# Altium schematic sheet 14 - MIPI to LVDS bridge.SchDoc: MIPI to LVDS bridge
size A3; PageSetup: Record=PageOptions¦CenterHorizontal=True¦CenterVertical=True¦PrintScale=0.70¦XCorrection=1.00¦YCorrection=1.00¦PrintKind=0¦BorderSize=5000000¦LeftOffset=0¦BottomOffset=0¦Orientation=2¦PaperLength=4200¦PaperWidth=2970¦Scale=100¦PaperSource=7¦PrintQuality=600¦MediaType=1¦DitherType=10¦PaperKind=A4¦PrintScaleMode=1; Author: Juan Anzola; SheetNumber: 14; SheetTotal: 21
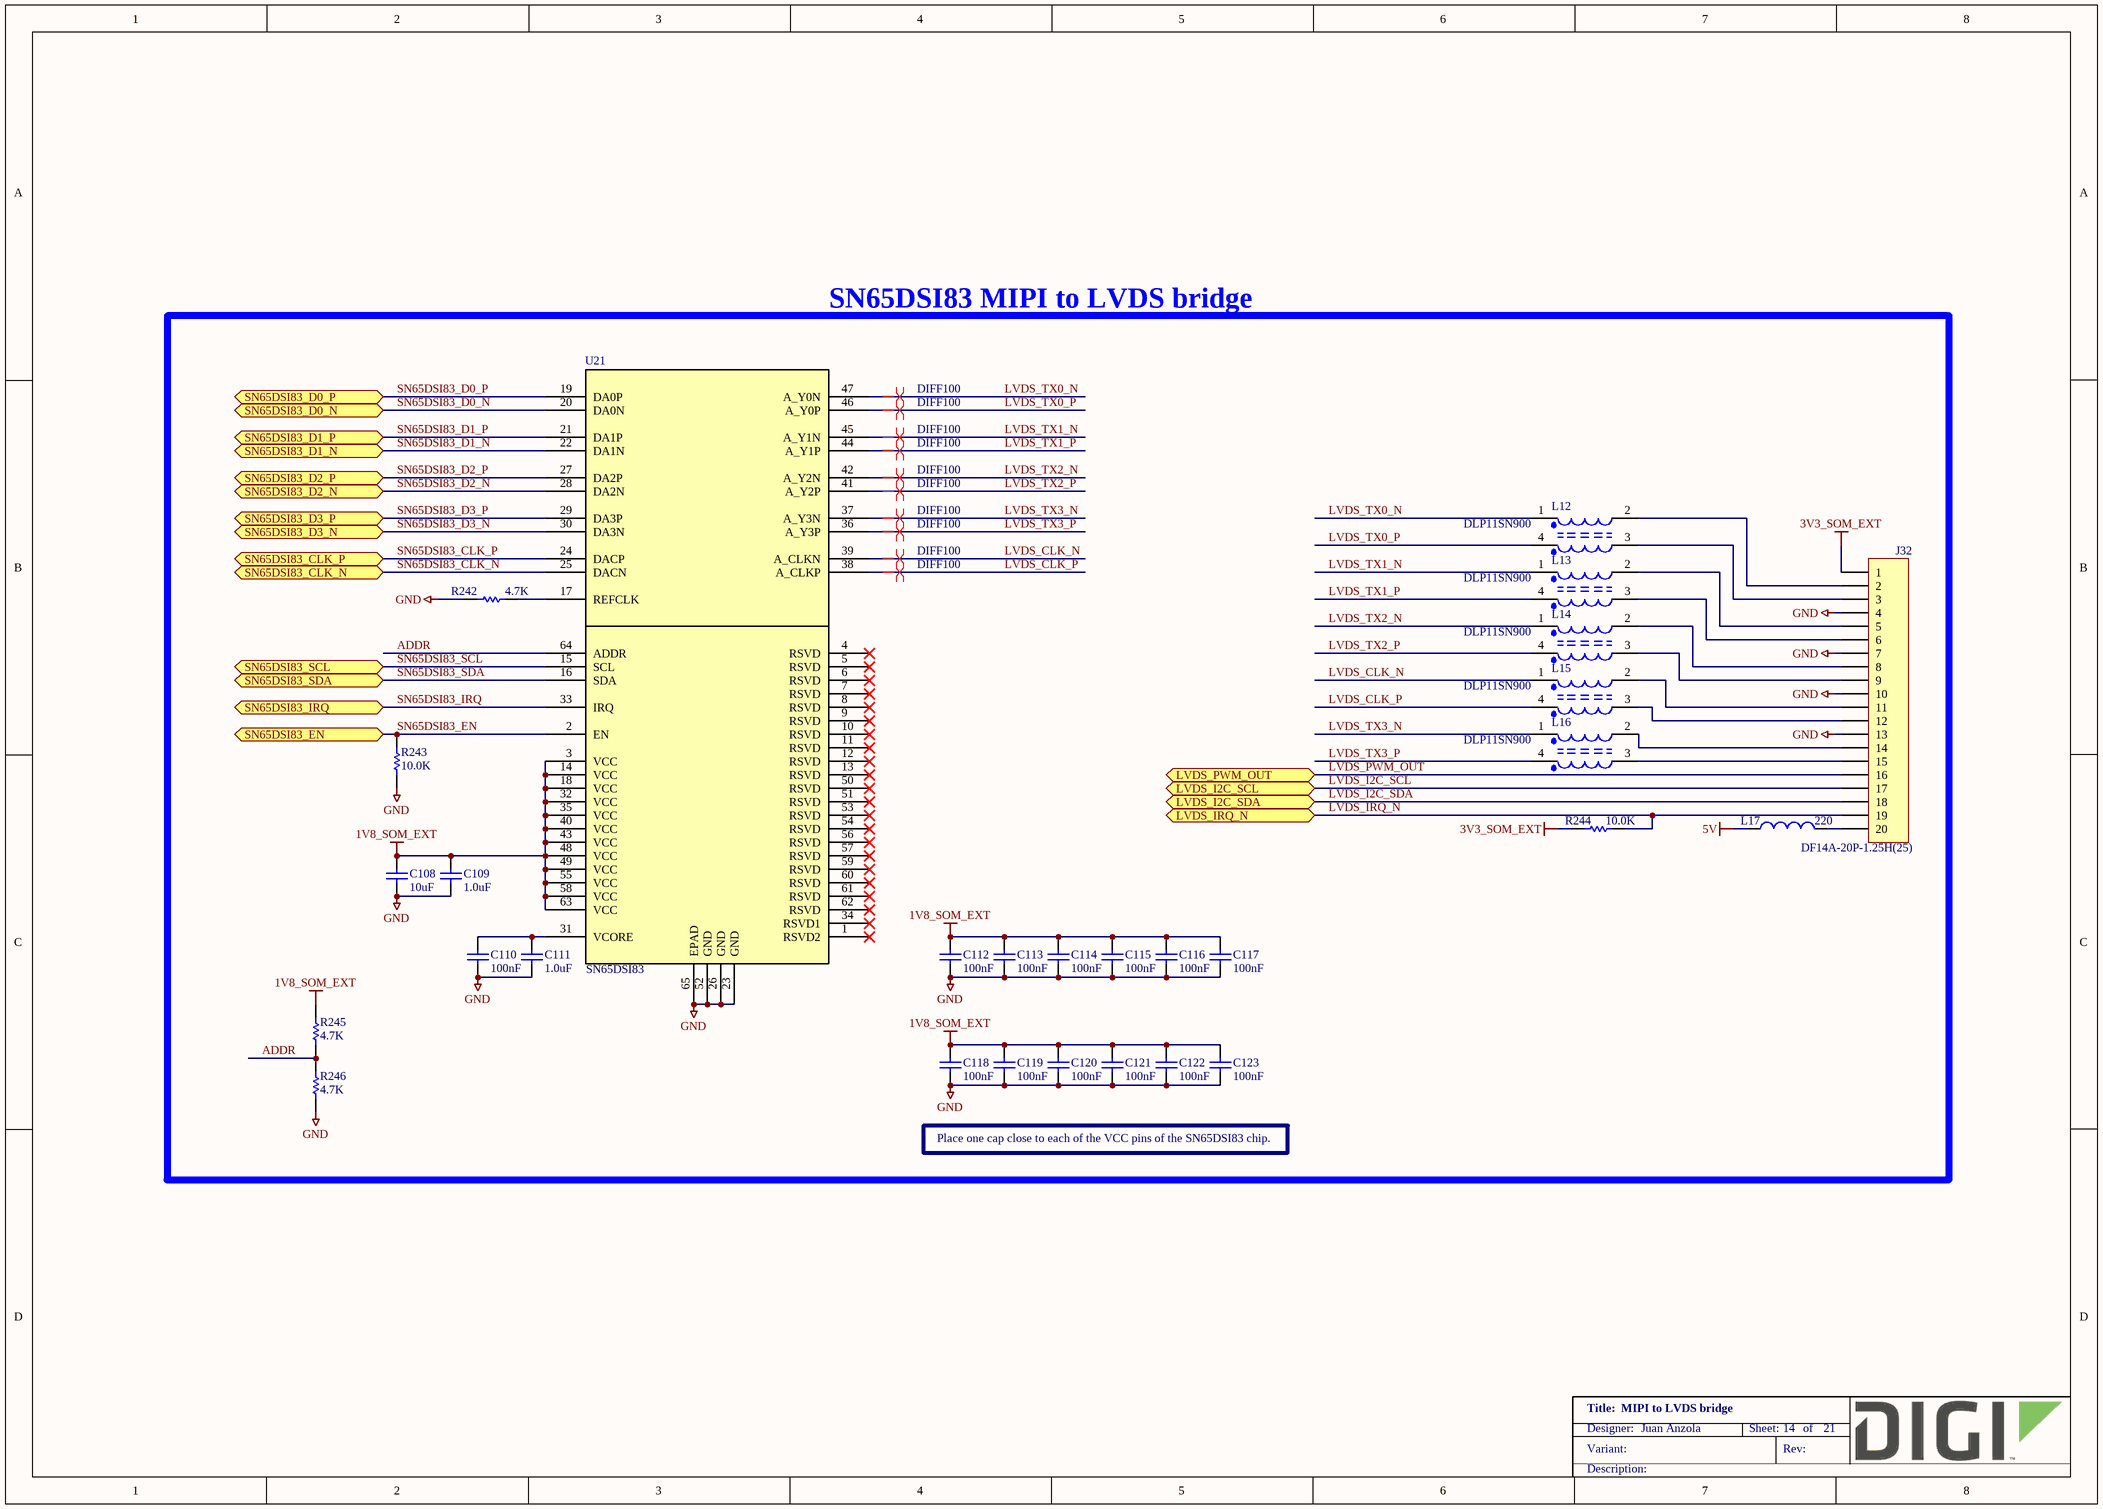
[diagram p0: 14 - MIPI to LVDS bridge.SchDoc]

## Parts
C108  10uF  [CAPC1005X55N]
C109  1.0uF  [CAPC1005X55N]
C110  100nF  [CAPC1005X55N]
C111  1.0uF  [CAPC1005X55N]
C112  100nF  [CAPC1005X55N]
C113  100nF  [CAPC1005X55N]
C114  100nF  [CAPC1005X55N]
C115  100nF  [CAPC1005X55N]
C116  100nF  [CAPC1005X55N]
C117  100nF  [CAPC1005X55N]
C118  100nF  [CAPC1005X55N]
C119  100nF  [CAPC1005X55N]
C120  100nF  [CAPC1005X55N]
C121  100nF  [CAPC1005X55N]
C122  100nF  [CAPC1005X55N]
C123  100nF  [CAPC1005X55N]
J32  DF14A-20P-1.25H(25)  [HIROSE_DF14A-20P-1.25H]
L12  DLP11SN900  [FIL_DLP11S]
L13  DLP11SN900  [FIL_DLP11S]
L14  DLP11SN900  [FIL_DLP11S]
L15  DLP11SN900  [FIL_DLP11S]
L16  DLP11SN900  [FIL_DLP11S]
L17  220  [INDC2013X110N]
R242  4.7K  [RESC1005X40N]
R243  10.0K  [RESC1005X40N]
R244  10.0K  [RESC1005X40N]
R245  4.7K  [RESC1005X40N]
R246  4.7K  [RESC1005X40N]
U21  SN65DSI83  [QFP50P1200X1200X120-65L30T320N]

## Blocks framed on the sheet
SN65DSI83 MIPI to LVDS bridge: C108-C123 J32 L12-L17 R242-R246 U21

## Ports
LVDS_I2C_SCL (bidir), LVDS_I2C_SDA (bidir), LVDS_IRQ_N (bidir), LVDS_PWM_OUT (bidir), SN65DSI83_CLK_N (bidir), SN65DSI83_CLK_P (bidir), SN65DSI83_D0_N (bidir), SN65DSI83_D0_P (bidir), SN65DSI83_D1_N (bidir), SN65DSI83_D1_P (bidir), SN65DSI83_D2_N (bidir), SN65DSI83_D2_P (bidir), SN65DSI83_D3_N (bidir), SN65DSI83_D3_P (bidir), SN65DSI83_EN (bidir), SN65DSI83_IRQ (bidir), SN65DSI83_SCL (bidir), SN65DSI83_SDA (bidir)

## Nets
1V8_SOM_EXT: C108.2 C109.2 C112.2 C113.2 C114.2 C115.2 C116.2 C117.2 C118.2 C119.2 C120.2 C121.2 C122.2 C123.2 R245.2 U21.3(VCC) U21.14(VCC) U21.18(VCC) U21.32(VCC) U21.35(VCC) U21.40(VCC) U21.43(VCC) U21.48(VCC) U21.49(VCC) U21.55(VCC) U21.58(VCC) U21.63(VCC)
3V3_SOM_EXT: J32.1 R244.1
5V: L17.1
GND: C108.1 C109.1 C110.2 C111.1 C112.1 C113.1 C114.1 C115.1 C116.1 C117.1 C118.1 C119.1 C120.1 C121.1 C122.1 C123.1 J32.4 J32.7 J32.10 J32.13 R242.2 R243.1 R246.1 U21.23(GND) U21.26(GND) U21.52(GND) U21.65(EPAD)
ADDR: R245.1 R246.2 U21.64(ADDR)
LVDS_CLK_N: L15.1 U21.39(A_CLKN)
LVDS_CLK_P: L15.4 U21.38(A_CLKP)
LVDS_I2C_SCL: J32.17 ; port LVDS_I2C_SCL
LVDS_I2C_SDA: J32.18 ; port LVDS_I2C_SDA
LVDS_IRQ_N: J32.19 R244.2 ; port LVDS_IRQ_N
LVDS_PWM_OUT: J32.16 ; port LVDS_PWM_OUT
LVDS_TX0_N: L12.1 U21.47(A_Y0N)
LVDS_TX0_P: L12.4 U21.46(A_Y0P)
LVDS_TX1_N: L13.1 U21.45(A_Y1N)
LVDS_TX1_P: L13.4 U21.44(A_Y1P)
LVDS_TX2_N: L14.1 U21.42(A_Y2N)
LVDS_TX2_P: L14.4 U21.41(A_Y2P)
LVDS_TX3_N: L16.1 U21.37(A_Y3N)
LVDS_TX3_P: L16.4 U21.36(A_Y3P)
SN65DSI83_CLK_N: U21.25(DACN) ; port SN65DSI83_CLK_N
SN65DSI83_CLK_P: U21.24(DACP) ; port SN65DSI83_CLK_P
SN65DSI83_D0_N: U21.20(DA0N) ; port SN65DSI83_D0_N
SN65DSI83_D0_P: U21.19(DA0P) ; port SN65DSI83_D0_P
SN65DSI83_D1_N: U21.22(DA1N) ; port SN65DSI83_D1_N
SN65DSI83_D1_P: U21.21(DA1P) ; port SN65DSI83_D1_P
SN65DSI83_D2_N: U21.28(DA2N) ; port SN65DSI83_D2_N
SN65DSI83_D2_P: U21.27(DA2P) ; port SN65DSI83_D2_P
SN65DSI83_D3_N: U21.30(DA3N) ; port SN65DSI83_D3_N
SN65DSI83_D3_P: U21.29(DA3P) ; port SN65DSI83_D3_P
SN65DSI83_EN: R243.2 U21.2(EN) ; port SN65DSI83_EN
SN65DSI83_IRQ: U21.33(IRQ) ; port SN65DSI83_IRQ
SN65DSI83_SCL: U21.15(SCL) ; port SN65DSI83_SCL
SN65DSI83_SDA: U21.16(SDA) ; port SN65DSI83_SDA
NetC110_1: C110.1 C111.2 U21.31(VCORE)
NetJ32_2: J32.2 L12.2
NetJ32_3: J32.3 L12.3
NetJ32_5: J32.5 L13.2
NetJ32_6: J32.6 L13.3
NetJ32_8: J32.8 L14.2
NetJ32_9: J32.9 L14.3
NetJ32_11: J32.11 L15.2
NetJ32_12: J32.12 L15.3
NetJ32_14: J32.14 L16.2
NetJ32_15: J32.15 L16.3
NetJ32_20: J32.20 L17.2
NetR242_1: R242.1 U21.17(REFCLK)

Not connected (* = marked no-connect by the designer): U21 1(RSVD2)* 4(RSVD)* 5(RSVD)* 6(RSVD)* 7(RSVD)* 8(RSVD)* 9(RSVD)* 10(RSVD)* 11(RSVD)* 12(RSVD)* 13(RSVD)* 34(RSVD1)* 50(RSVD)* 51(RSVD)* 53(RSVD)* 54(RSVD)* 56(RSVD)* 57(RSVD)* 59(RSVD)* 60(RSVD)* 61(RSVD)* 62(RSVD)*

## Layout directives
differential pair; net class DIFF100: LVDS_CLK_N, LVDS_CLK_P, LVDS_TX0_N, LVDS_TX0_P, LVDS_TX1_N, LVDS_TX1_P, LVDS_TX2_N, LVDS_TX2_P, LVDS_TX3_N, LVDS_TX3_P

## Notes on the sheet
- Place one cap close to each of the VCC pins of the SN65DSI83 chip.

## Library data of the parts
C108 = 1001168: CAP CER 10UF 10V 20% X5R 0402; Part_Type: Capacitor; Manufacturer: Samsung; Manufacturer_Part_Number: CL05A106MP5NUNC; Digi_PN: 14050689; Component_Life_Cycle_State: Reviewed; Area: 0.95; Project: CCWMX6_SBC board
C109 C111 = 1001167: CAP CER 1UF 10V 10% X5R 0402; Part_Type: Capacitor; Manufacturer: Murata; Manufacturer_Part_Number: GRM155R61A105KE15D; Digi_PN: 14050399; Component_Life_Cycle_State: Reviewed; Area: 0.95; Project: CCWMX6_SBC board
C110 C112-C123 = 1000006: CAP 100nF 16V 10% X7R 0402; Part_Type: Capacitor; Manufacturer: Murata; Manufacturer_Part_Number: GRM155R71C104KA88D; Component_Life_Cycle_State: CAD Reviewed; Area: 0.95; Project: KITT; Tolerance: 10; Digi_PN: 14050552
J32 = 1001132: CONN HEADER 20POS 1.25MM R/A SMD; Part_Type: Connector; Manufacturer: Hirose; Digi_PN: 18050231; Component_Life_Cycle_State: Reviewed; Area: 206.34; Project: CCWMX6_SBC board
L12-L16 = 1001014: CHOKE COIL COMMON MODE 150MA SMD; Part_Type: Inductor; Manufacturer: Murata; Manufacturer_Part_Number: DLP11SN900HL2L; Component_Life_Cycle_State: Reviewed; Area: 3.94; Project: ResMed RF Test Interface Board; Digi_PN: 21000531
L17 = 1001174: FERRITE BEAD 220 OHM 2.0A 0805; Manufacturer: Wurth Electronics Inc; Manufacturer_Part_Number: 742792022; Digi_PN: 21000146; Component_Life_Cycle_State: Reviewed; Area: 4.24; Project: CCWMX6_SBC board
R242 R245 R246 = 1000038: RES 4.7K OHM 1/10W 5% 0402 SMD; Part_Type: Resistor; Manufacturer: Panasonic - ECG; Manufacturer_Part_Number: ERJ-2GEJ472X; Digi_PN: 13050549; Component_Life_Cycle_State: Proven; Area: 0,95; Project: Adjustable Foundation; Power_WV_SRF: 100; Tolerance: 5
R243 R244 = 1000537: RES 10.0K OHM 1/10W 1% 0402 SMD; Part_Type: Resistor; Manufacturer: Panasonic - ECG; Manufacturer_Part_Number: ERJ-2RKF1002X; Component_Life_Cycle_State: CAD Reviewed; Area: 0.95; Project: KITT; Power_WV_SRF: 100; Digi_PN: 13051084
U21 = 1002718: IC BRIDGE DSI TO LVDS 64HTQFP; Manufacturer: Texas Instruments; Digi_PN: 16000196; Component_Life_Cycle_State: Pending; Area: 180,9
